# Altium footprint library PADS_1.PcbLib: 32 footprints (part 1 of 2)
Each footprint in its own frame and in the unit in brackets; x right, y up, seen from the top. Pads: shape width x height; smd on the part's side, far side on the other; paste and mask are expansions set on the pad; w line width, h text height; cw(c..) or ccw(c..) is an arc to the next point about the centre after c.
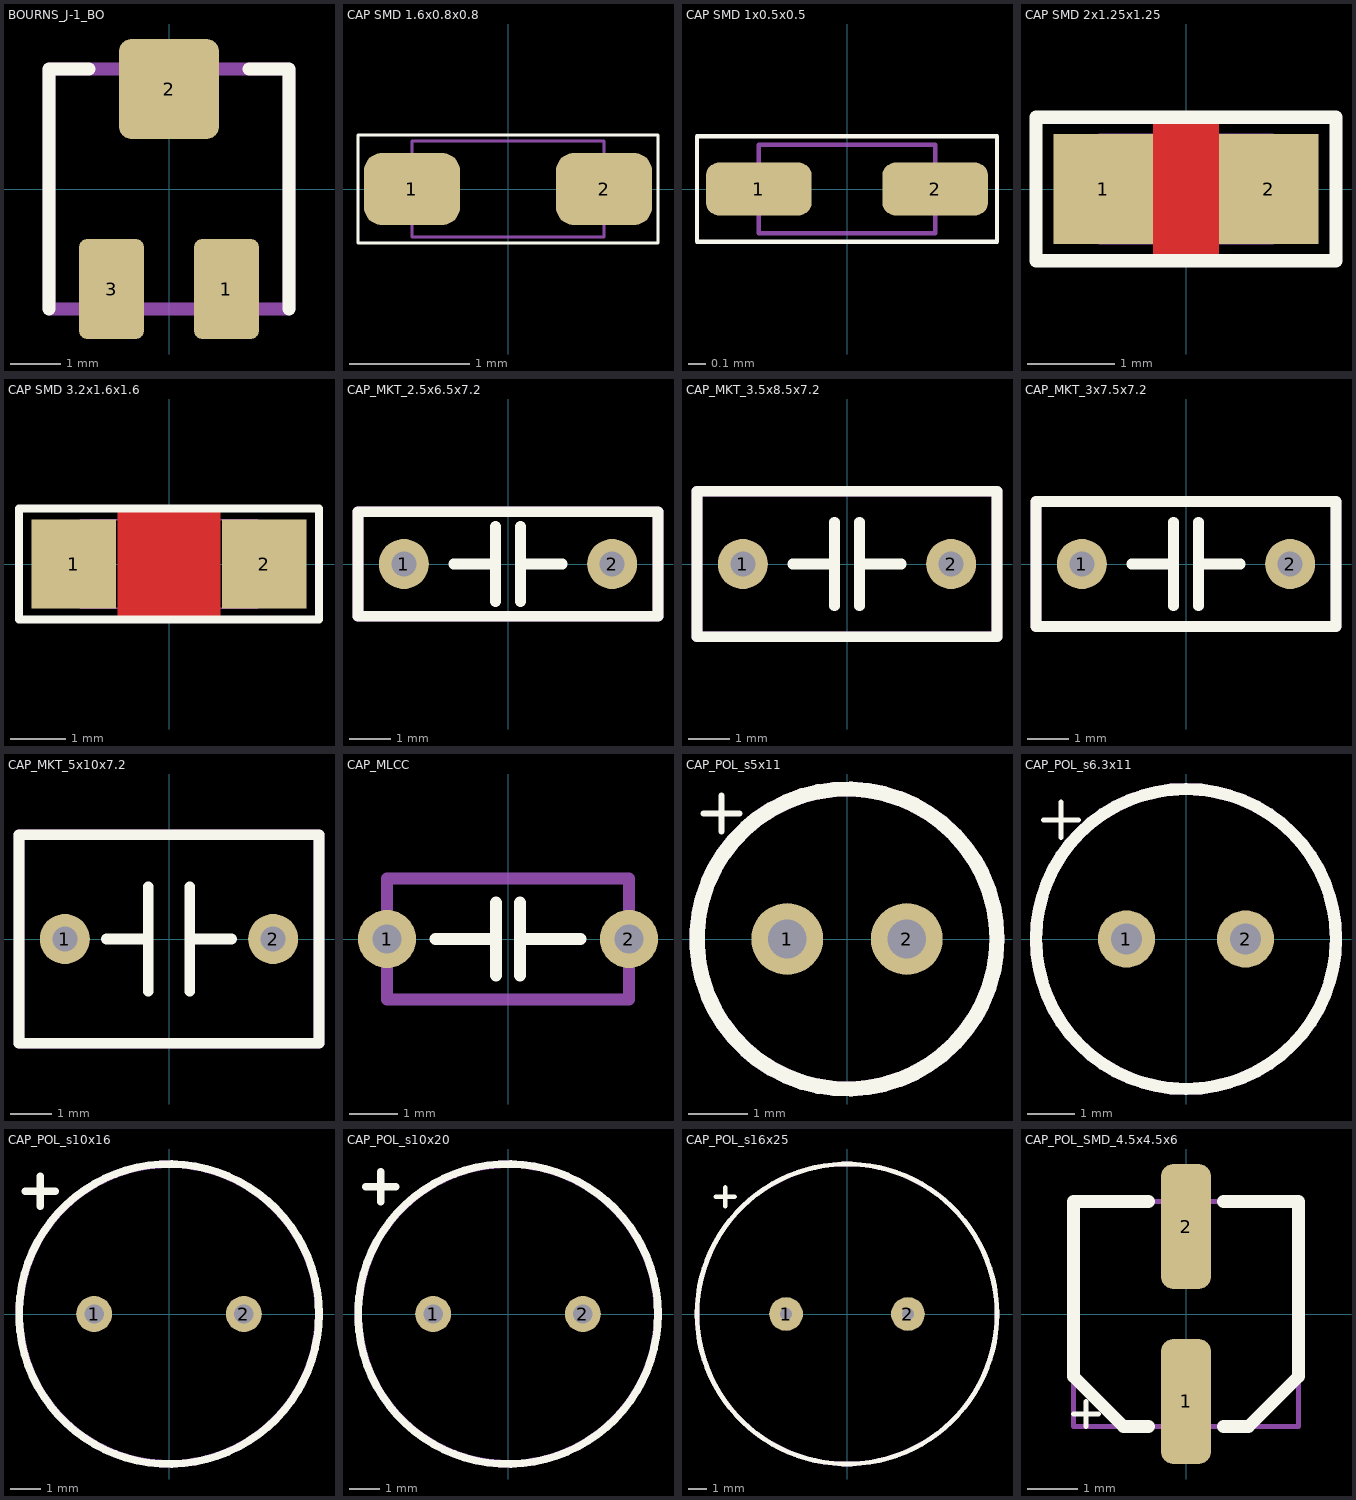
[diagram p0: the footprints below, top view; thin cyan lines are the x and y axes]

## BOURNS_J-1_BO [mm]
height 2.8
pads (3):
  rrect25% 1.3x2 smd: 1(1.15,-2) 3(-1.15,-2)
  rrect25% 2x2 smd: 2(0,2)
Top Overlay:
  lines w0.254: -2.4,-2.4 -2.4,2.4 -1.6,2.4 ; 1.6,2.4 2.4,2.4 2.4,-2.4
Mechanical 13:
  lines w0.254: -2.4,-2.4 -2.4,2.4 2.4,2.4 2.4,-2.4 -2.4,-2.4
3D body: height 2.8, standoff 0, extent -2.4,-2.4 2.4,2.4

## CAP SMD 1.6x0.8x0.8 [mm]
height 0.8
pads (2):
  rrect50% 0.8x0.6 smd: 1(-0.8,0) 2(0.8,0)
Top Overlay:
  lines w0.025: -1.25,-0.45 -1.25,0.45 1.25,0.45 1.25,-0.45 -1.25,-0.45
Mechanical 13:
  lines w0.025: -0.8,-0.4 0.8,-0.4 0.8,0.4 -0.8,0.4 -0.8,-0.4
3D body: height 0.8, standoff 0, extent -0.35,-0.4 0.35,0.4
3D body: height 0.8, standoff 0, extent -0.8,-0.4 -0.35,0.4
3D body: height 0.8, standoff 0, extent 0.35,-0.4 0.8,0.4

## CAP SMD 1x0.5x0.5 [mm]
height 0.5
pads (2):
  rrect50% 0.6x0.3 smd: 1(-0.5,0) 2(0.5,0)
Top Overlay:
  lines w0.025: -0.85,-0.3 -0.85,0.3 0.85,0.3 0.85,-0.3 -0.85,-0.3
Mechanical 13:
  lines w0.025: -0.5,-0.25 0.5,-0.25 0.5,0.25 -0.5,0.25 -0.5,-0.25
3D body: height 0.5, standoff 0, extent -0.5,-0.25 -0.2,0.25
3D body: height 0.5, standoff 0, extent 0.2,-0.25 0.5,0.25
3D body: height 0.5, standoff 0, extent -0.2,-0.25 0.2,0.25

## CAP SMD 2x1.25x1.25 [mil]
height 49.21
pads (2):
  rect 45x50 smd: 1(-37.5,0) 2(37.5,0)
Top Layer:
  pour cut-out: -14.76,32.48 14.76,32.48 14.76,-32.48 -14.76,-32.48
Top Overlay:
  lines w5.91: -67.91,-32.48 -67.91,32.48 67.91,32.48 67.91,-32.48 -67.91,-32.48
Mechanical 13:
  lines w1: -39.37,-24.61 39.37,-24.61 39.37,24.61 -39.37,24.61 -39.37,-24.61
3D body: height 49.21, standoff 0, extent -19.68,-24.6 19.69,24.61
3D body: height 49.21, standoff 0, extent -39.37,-24.61 -19.69,24.61
3D body: height 49.21, standoff 0, extent 19.68,-24.6 39.37,24.61

## CAP SMD 3.2x1.6x1.6 [mil]
height 62.99
pads (2):
  rect 60x63 smd: 1(-67.5,0) 2(67.5,0)
Top Layer:
  pour cut-out: -36.42,39.37 35.43,39.37 36.42,38.39 36.42,-39.37 -36.42,-39.37
Top Overlay:
  lines w5.91: -106.3,-39.37 106.3,-39.37 106.3,39.37 -106.3,39.37 -106.3,-39.37
Mechanical 13:
  lines w1: -62.99,-31.5 -62.99,31.5 62.99,31.5 62.99,-31.5 -62.99,-31.5
3D body: height 62.99, standoff 0, extent -35.43,-31.5 35.43,31.5
3D body: height 62.99, standoff 0, extent -62.99,-31.5 -35.43,31.5
3D body: height 62.99, standoff 0, extent 35.43,-31.49 62.99,31.5

## CAP_MKT_2.5x6.5x7.2 [mm] "Raster 5"
height 6.5
pads (2):
  round 1.2 hole 0.6: 1(-2.5,0) 2(2.5,0)
Top Overlay:
  lines w0.254: -1.3,0 -0.3,0 ; -0.3,-0.9 -0.3,0.9 ; 0.3,-0.9 0.3,0.9 ; 0.3,0 1.3,0 ; -3.6,-1.25 -3.6,1.25 3.6,1.25 3.6,-1.25 1.3,-1.25 -1.3,-1.25 -2.65,-1.25 -3.6,-1.25
Mechanical 13:
  lines w0.254: -3.6,-1.25 -3.6,1.25 3.6,1.25 3.6,-1.25 -3.6,-1.25
3D body: height 6.5, standoff 0, extent -3.6,-1.25 3.6,1.25
3D body: height 0, standoff -3, extent 2.252,-0.25 2.75,0.25
3D body: height 0, standoff -3, extent -2.748,-0.249 -2.25,0.25

## CAP_MKT_3.5x8.5x7.2 [mm] "Raster 5"
height 8.5
pads (2):
  round 1.2 hole 0.6: 1(-2.5,0) 2(2.5,0)
Top Overlay:
  lines w0.254: -1.3,0 -0.3,0 ; -0.3,-1 -0.3,1 ; 0.3,-1 0.3,1 ; 0.3,0 1.3,0 ; -3.6,-1.75 3.6,-1.75 3.6,1.75 -3.6,1.75 -3.6,-1.75
Mechanical 13:
  lines w0.254: -3.6,-1.75 3.6,-1.75 3.6,1.75 -3.6,1.75 -3.6,-1.75
3D body: height 0, standoff -3, extent -2.748,-0.249 -2.25,0.25
3D body: height 0, standoff -3, extent 2.252,-0.25 2.75,0.25
3D body: height 8.5, standoff 0, extent -3.6,-1.75 3.6,1.75

## CAP_MKT_3x7.5x7.2 [mm] "Raster 5"
height 5
pads (2):
  round 1.2 hole 0.6: 1(-2.5,0) 2(2.5,0)
Top Overlay:
  lines w0.254: -1.3,0 -0.3,0 ; -0.3,-1 -0.3,1 ; 0.3,-1 0.3,1 ; 0.3,0 1.3,0 ; -3.6,-1.5 3.6,-1.5 3.6,1.5 -3.6,1.5 -3.6,-1.5
Mechanical 13:
  lines w0.254: -3.6,-1.5 3.6,-1.5 3.6,1.5 -3.6,1.5 -3.6,-1.5
3D body: height 0, standoff -3, extent -2.748,-0.249 -2.25,0.25
3D body: height 0, standoff -3, extent 2.252,-0.25 2.75,0.25
3D body: height 7.5, standoff 0, extent -3.6,-1.5 3.6,1.5

## CAP_MKT_5x10x7.2 [mm] "Raster 5"
height 10
pads (2):
  round 1.2 hole 0.6: 1(-2.5,0) 2(2.5,0)
Top Overlay:
  lines w0.254: -1.5,0 -0.5,0 ; -0.5,-1.25 -0.5,-0.75 -0.5,0 ; -0.5,1.25 -0.5,0.75 -0.5,0 ; 0.5,-1.25 0.5,-0.75 0.5,0.75 0.5,1.25 ; 0.5,0 1.5,0 ; -3.6,-2.5 3.6,-2.5 3.6,2.5 -3.6,2.5 -3.6,-2.5
Mechanical 13:
  lines w0.254: -3.6,-2.5 3.6,-2.5 3.6,2.5 -3.6,2.5 -3.6,-2.5
3D body: height 10, standoff 0, extent -3.6,-2.5 3.6,2.5
3D body: height 0, standoff -3, extent -2.748,-0.25 -2.25,0.25
3D body: height 0, standoff -3, extent 2.252,-0.25 2.75,0.25

## CAP_MLCC [mm] "Raster 5"
pads (2):
  round 1.2 hole 0.6: 1(-2.5,0) 2(2.5,0)
Top Overlay:
  lines w0.254: -1.5,0 -0.25,0 ; -0.25,-0.75 -0.25,0.75 ; 0.25,-0.75 0.25,0.75 ; 0.25,0 0.5,0 1.5,0
Mechanical 13:
  lines w0.254: -2.5,-1.25 2.5,-1.25 2.5,1.25 -2.5,1.25 -2.5,0 -2.5,-1.25
3D body "User Library-Cer-Cap2_5 (5x1_5).STEP": height 5.3, standoff -2.7, extent -2.919,-1.699 2.919,1.7

## CAP_POL_s5x11 [mm] "Raster 2"
height 11
pads (2):
  round 1.2 hole 0.65: 1(-1,0) 2(1,0)
Top Overlay:
  circle w0.254: c0,0 r2.508
  lines w0.1: -2.4,2.1 -1.8,2.1 ; -2.1,1.8 -2.1,2.4
Mechanical 13:
  circle w0.254: c0,0 r2.508
3D body: height 11, standoff 0, extent -2.5,-2.497 2.5,2.497
3D body: height 0, standoff -3, extent -1.248,-0.249 -0.75,0.25
3D body: height 0, standoff -3, extent 0.752,-0.25 1.25,0.25

## CAP_POL_s6.3x11 [mm] "Raster 2.5"
height 11
pads (2):
  round 1.2 hole 0.65: 1(-1.25,0) 2(1.25,0)
Top Overlay:
  circle w0.254: c0,0 r3.15
  lines w0.1: -3,2.5 -2.25,2.5 ; -2.625,2.125 -2.625,2.875
Mechanical 13:
  circle w0.254: c0,0 r3.15
3D body: height 0, standoff -3, extent 1,-0.249 1.498,0.25
3D body: height 0, standoff -3, extent -1.5,-0.249 -1.002,0.25
3D body: height 11, standoff 0, extent -3.15,-3.147 3.15,3.147

## CAP_POL_s10x16 [mm] "Raster 5"
height 16
pads (2):
  round 1.2 hole 0.65: 1(-2.5,0) 2(2.5,0)
Top Overlay:
  circle w0.254: c0,0 r5.009
  lines w0.254: -4.8,4.1 -3.8,4.1 ; -4.3,3.6 -4.3,4.6
Mechanical 13:
  circle w0.254: c0,0 r5.001
3D body: height 16, standoff 0, extent -5,-5 5,5
3D body: height 0, standoff -3, extent -2.748,-0.249 -2.25,0.25
3D body: height 0, standoff -3, extent 2.252,-0.25 2.75,0.25

## CAP_POL_s10x20 [mm] "Raster 5"
height 20
pads (2):
  round 1.2 hole 0.65: 1(-2.5,0) 2(2.5,0)
Top Overlay:
  circle w0.254: c0,0 r5.009
  lines w0.254: -4.75,4.25 -3.75,4.25 ; -4.25,3.75 -4.25,4.75
Mechanical 13:
  circle w0.254: c0,0 r5.001
3D body: height 0, standoff -3, extent 2.252,-0.25 2.75,0.25
3D body: height 0, standoff -3, extent -2.748,-0.249 -2.25,0.25
3D body: height 20, standoff 0, extent -5,-5 5,5

## CAP_POL_s16x25 [mm] "Raster 7.5"
height 25
pads (2):
  round 1.8 hole 0.65: 1(-3.25,0) 2(3.25,0)
Top Overlay:
  circle w0.254: c0,0 r8.002
  lines w0.254: -7,6.25 -6,6.25 ; -6.5,5.75 -6.5,6.75
Mechanical 13:
  circle w0.254: c0,0 r8.001
3D body: height 25, standoff 0, extent -8,-8 8,8
3D body: height 0, standoff -3, extent -3.498,-0.25 -3,0.25
3D body: height 0, standoff -3, extent 3,-0.25 3.498,0.25

## CAP_POL_SMD_4.5x4.5x6 [mm]
height 6
pads (2):
  rrect50% 1x2.5 smd: 1(0,-1.75) 2(0,1.75)
Top Overlay:
  lines w0.1: -2.25,-2 -1.75,-2 ; -2,-2.25 -2,-1.75
  lines w0.254: -0.75,-2.25 -1.25,-2.25 -2.25,-1.25 -2.25,2.25 -0.75,2.25 ; 0.75,-2.25 1.25,-2.25 2.25,-1.25 2.25,2.25 0.75,2.25
Mechanical 13:
  lines w0.1: -2.25,-1.25 -1.25,-2.25 ; 1.25,-2.25 2.25,-1.25 ; -2.25,-2.25 -2.25,2.25 0,2.25 2.25,2.25 2.25,-2.25 0,-2.25 -2.25,-2.25
3D body: height 0.3, standoff 0, extent -0.375,-2.75 0.375,-0.75
3D body: height 0.3, standoff 0, extent -0.375,0.75 0.375,2.75
3D body: height 6, standoff 1.8, extent -2.25,-2.247 2.25,2.247
3D body: height 1.2, standoff 0.3, extent -2.275,-2.275 2.25,2.25
3D body: height 1.5, standoff 0.3, extent -2.25,-2.247 2.25,2.247
3D body: height 4, standoff 1, extent -2.1,-2.1 2.1,2.1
